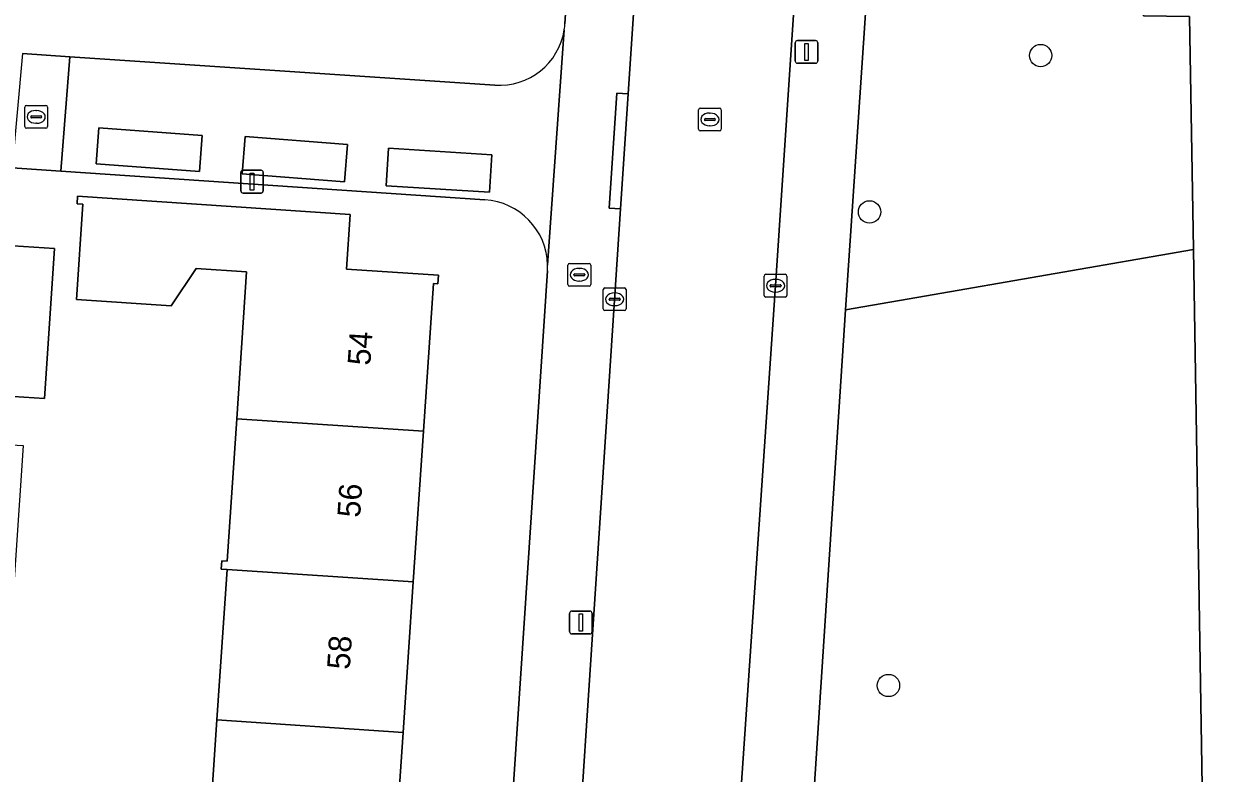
# Model space of a CAD drawing. Extents: x 161848 to 162726, y 385382 to 386521.
# Drawn here: x 162105.8 to 162158.3, y 385774.9 to 385807.8 of the extents above; entities that cross this region are included whole.
import ezdxf

# ---------------------------------------------------------------- set-up
doc = ezdxf.new("R2010")
doc.units = 0
for name, color, linetype in [('IMGEO_Boom', 7, 'Continuous'), ('IMGEO_Brandkraan', 7, 'Continuous'), ('IMGEO_Erf', 7, 'Continuous'), ('IMGEO_Groenvoorziening', 7, 'Continuous'), ('IMGEO_Kolk', 7, 'Continuous'), ('IMGEO_Lichtmast', 7, 'Continuous'), ('IMGEO_Pand', 7, 'Continuous'), ('IMGEO_Pand_nummerreeks', 7, 'Continuous'), ('IMGEO_Parkeervlak_open', 7, 'Continuous'), ('IMGEO_Rijbaan_lokaal_open', 7, 'Continuous'), ('IMGEO_Rioolput', 7, 'Continuous'), ('IMGEO_Voetpad_halfverhard', 7, 'Continuous'), ('IMGEO_Voetpad_open', 7, 'Continuous'), ('IMGEO_Woonerf_open', 7, 'Continuous')]:
    doc.layers.add(name, color=color, linetype=linetype)

msp = doc.modelspace()

# ---------------------------------------------------------------- linework, layer by layer
at = {"layer": 'IMGEO_Boom'}
for centre in [(162150.402, 385806.424), (162142.896, 385799.563), (162143.726, 385778.781)]:
    msp.add_circle(centre, 0.489, dxfattribs=at)
at = {"layer": 'IMGEO_Brandkraan'}
for p, q in [((162129.663, 385796.378), (162129.663, 385797.23)), ((162129.738, 385797.304), (162130.59, 385797.304)), ((162130.151, 385797.084), (162130.176, 385797.084)), ((162130.664, 385797.23), (162130.664, 385796.378)), ((162129.922, 385796.798), (162129.922, 385796.81)), ((162130.36, 385796.761), (162129.962, 385796.761)), ((162129.965, 385796.847), (162130.363, 385796.847)), ((162130.174, 385796.524), (162130.149, 385796.524)), ((162130.406, 385796.81), (162130.406, 385796.798)), ((162130.59, 385796.304), (162129.738, 385796.304))]:
    msp.add_line(p, q, dxfattribs=at)
for points in [[(162129.663, 385796.378), (162129.663, 385797.23)], [(162129.738, 385797.304), (162130.59, 385797.304)], [(162130.664, 385797.23), (162130.664, 385796.378)], [(162130.59, 385796.304), (162129.738, 385796.304)]]:
    msp.add_lwpolyline(points, dxfattribs=at)
for centre, radius, start, end in [((162129.74, 385797.228), 0.0765, 91.552, 178.448), ((162129.74, 385797.228), 0.0765, 91.552, 178.448), ((162130.588, 385797.228), 0.0765, 1.552, 88.448), ((162130.588, 385797.228), 0.0765, 1.552, 88.448), ((162129.962, 385796.807), 0.0403, 85.8775, 175.7526), ((162129.959, 385796.797), 0.0366, 178.938, 274.7102), ((162130.363, 385796.804), 0.043, 264.8664, 352.4533), ((162130.367, 385796.809), 0.0386, 1.7309, 96.639), ((162129.74, 385796.38), 0.0765, 181.552, 268.448), ((162129.74, 385796.38), 0.0765, 181.552, 268.448), ((162130.588, 385796.38), 0.0765, 271.552, 358.448), ((162130.588, 385796.38), 0.0765, 271.552, 358.448)]:
    msp.add_arc(centre, radius, start, end, dxfattribs=at)
for centre, major_axis, ratio, start_param, end_param in [((162130.15, 385796.804), (-0.387, 0.002), 0.722429, 4.712389, 7.853982), ((162130.175, 385796.804), (-0.39, 0.002), 0.717154, 1.570796, 4.712389)]:
    msp.add_ellipse(centre, major_axis=major_axis, ratio=ratio, start_param=start_param, end_param=end_param, dxfattribs=at)
at = {"layer": 'IMGEO_Erf'}
for points in [[(162129.533, 385807.812), (162132.809, 385856.832)], [(162105.74, 385806.512), (162107.807, 385806.373), (162126.458, 385805.124)], [(162126.021, 385800.096), (162107.418, 385801.352), (162105.286, 385801.495), (162104.182, 385801.57), (162103.952, 385798.168), (162107.135, 385797.957), (162106.7, 385791.372), (162103.517, 385791.583), (162103.367, 385789.451), (162105.762, 385789.318), (162105.439, 385784.505), (162105.109, 385779.574), (162102.716, 385779.735), (162102.474, 385776.123), (162104.871, 385776.017), (162104.554, 385771.291), (162104.23, 385766.445), (162101.833, 385766.551), (162100.851, 385751.751), (162123.16, 385750.258)], [(162113.836, 385770.929), (162114.264, 385777.274), (162114.709, 385783.871), (162114.456, 385783.888), (162114.48, 385784.253), (162114.711, 385784.237), (162115.133, 385790.489), (162115.568, 385796.933), (162113.349, 385797.082), (162112.251, 385795.446), (162108.101, 385795.726), (162108.383, 385799.9), (162108.129, 385799.917), (162108.152, 385800.25), (162120.107, 385799.443), (162119.946, 385797.053), (162123.981, 385796.781), (162123.956, 385796.404), (162123.761, 385796.417), (162123.324, 385789.937), (162122.878, 385783.33), (162122.432, 385776.723), (162121.986, 385770.116)], [(162125.095, 385750.985), (162125.671, 385751.883), (162125.822, 385752.589), (162128.766, 385796.974)]]:
    msp.add_lwpolyline(points, dxfattribs=at)
for centre, radius, start, end in [((162126.654, 385808.002), 2.885, 266.096, 351.118), ((162126.828, 385807.98), 2.71, 351.0214, 356.4462), ((162125.84, 385797.169), 2.932, 1.1876, 86.4666), ((162126.038, 385797.166), 2.734, 355.9736, 1.3412)]:
    msp.add_arc(centre, radius, start, end, dxfattribs=at)
at = {"layer": 'IMGEO_Groenvoorziening'}
msp.add_lwpolyline([(162157.103, 385797.911), (162156.935, 385808.144), (162154.917, 385808.163), (162153.602, 385814.866), (162152.92, 385815.252), (162143.498, 385813.15), (162143.016, 385812.624), (162141.848, 385795.27), (162144.975, 385795.811)], close=True, dxfattribs=at)
msp.add_lwpolyline([(162141.331, 385748.75), (162142.003, 385748.615), (162152.519, 385747.611), (162152.549, 385749.34), (162152.561, 385750), (162152.889, 385768.789), (162157.58, 385768.924), (162157.103, 385797.911), (162144.975, 385795.811), (162141.848, 385795.27), (162138.994, 385751.625), (162139.021, 385751.25), (162139.116, 385750.837), (162139.274, 385750.446), (162139.555, 385750)], dxfattribs=at)
at = {"layer": 'IMGEO_Kolk'}
for p, q in [((162105.835, 385803.309), (162105.835, 385804.161)), ((162105.91, 385804.235), (162106.762, 385804.235)), ((162106.323, 385804.015), (162106.348, 385804.015)), ((162106.836, 385804.161), (162106.836, 385803.309)), ((162106.094, 385803.729), (162106.094, 385803.741)), ((162106.532, 385803.692), (162106.134, 385803.692)), ((162106.137, 385803.778), (162106.535, 385803.778)), ((162106.346, 385803.455), (162106.321, 385803.455)), ((162106.578, 385803.741), (162106.578, 385803.729)), ((162106.762, 385803.235), (162105.91, 385803.235)), ((162138.272, 385795.898), (162138.272, 385796.75)), ((162138.347, 385796.824), (162139.199, 385796.824)), ((162138.76, 385796.604), (162138.785, 385796.604)), ((162139.273, 385796.75), (162139.273, 385795.898)), ((162131.212, 385795.305), (162131.212, 385796.157)), ((162131.287, 385796.231), (162132.139, 385796.231)), ((162131.7, 385796.011), (162131.725, 385796.011)), ((162132.213, 385796.157), (162132.213, 385795.305)), ((162138.531, 385796.318), (162138.531, 385796.33)), ((162138.969, 385796.281), (162138.571, 385796.281)), ((162138.574, 385796.367), (162138.972, 385796.367)), ((162138.783, 385796.044), (162138.758, 385796.044)), ((162139.015, 385796.33), (162139.015, 385796.318)), ((162131.471, 385795.725), (162131.471, 385795.737)), ((162131.909, 385795.688), (162131.511, 385795.688)), ((162131.514, 385795.774), (162131.912, 385795.774)), ((162131.723, 385795.451), (162131.698, 385795.451)), ((162131.955, 385795.737), (162131.955, 385795.725)), ((162139.199, 385795.824), (162138.347, 385795.824)), ((162132.139, 385795.231), (162131.287, 385795.231))]:
    msp.add_line(p, q, dxfattribs=at)
for points in [[(162105.835, 385803.309), (162105.835, 385804.161)], [(162105.91, 385804.235), (162106.762, 385804.235)], [(162106.836, 385804.161), (162106.836, 385803.309)], [(162106.762, 385803.235), (162105.91, 385803.235)], [(162138.272, 385795.898), (162138.272, 385796.75)], [(162138.347, 385796.824), (162139.199, 385796.824)], [(162139.273, 385796.75), (162139.273, 385795.898)], [(162131.212, 385795.305), (162131.212, 385796.157)], [(162131.287, 385796.231), (162132.139, 385796.231)], [(162132.213, 385796.157), (162132.213, 385795.305)], [(162139.199, 385795.824), (162138.347, 385795.824)], [(162132.139, 385795.231), (162131.287, 385795.231)]]:
    msp.add_lwpolyline(points, dxfattribs=at)
for centre, radius, start, end in [((162105.912, 385804.159), 0.0765, 91.552, 178.448), ((162105.912, 385804.159), 0.0765, 91.552, 178.448), ((162106.76, 385804.159), 0.0765, 1.552, 88.448), ((162106.76, 385804.159), 0.0765, 1.552, 88.448), ((162105.912, 385803.311), 0.0765, 181.552, 268.448), ((162105.912, 385803.311), 0.0765, 181.552, 268.448), ((162106.134, 385803.738), 0.0403, 85.8775, 175.7526), ((162106.131, 385803.728), 0.0366, 178.938, 274.7102), ((162106.535, 385803.735), 0.043, 264.8664, 352.4533), ((162106.539, 385803.74), 0.0386, 1.7309, 96.639), ((162106.76, 385803.311), 0.0765, 271.552, 358.448), ((162106.76, 385803.311), 0.0765, 271.552, 358.448), ((162138.349, 385796.748), 0.0765, 91.552, 178.448), ((162138.349, 385796.748), 0.0765, 91.552, 178.448), ((162139.197, 385796.748), 0.0765, 1.552, 88.448), ((162139.197, 385796.748), 0.0765, 1.552, 88.448), ((162131.289, 385796.155), 0.0765, 91.552, 178.448), ((162131.289, 385796.155), 0.0765, 91.552, 178.448), ((162132.137, 385796.155), 0.0765, 1.552, 88.448), ((162132.137, 385796.155), 0.0765, 1.552, 88.448), ((162138.571, 385796.327), 0.0403, 85.8775, 175.7526), ((162138.568, 385796.317), 0.0366, 178.938, 274.7102), ((162138.972, 385796.324), 0.043, 264.8664, 352.4533), ((162138.976, 385796.329), 0.0386, 1.7309, 96.639), ((162131.511, 385795.734), 0.0403, 85.8775, 175.7526), ((162131.508, 385795.724), 0.0366, 178.938, 274.7102), ((162131.912, 385795.731), 0.043, 264.8664, 352.4533), ((162131.916, 385795.736), 0.0386, 1.7309, 96.639), ((162138.349, 385795.9), 0.0765, 181.552, 268.448), ((162138.349, 385795.9), 0.0765, 181.552, 268.448), ((162139.197, 385795.9), 0.0765, 271.552, 358.448), ((162139.197, 385795.9), 0.0765, 271.552, 358.448), ((162131.289, 385795.307), 0.0765, 181.552, 268.448), ((162131.289, 385795.307), 0.0765, 181.552, 268.448), ((162132.137, 385795.307), 0.0765, 271.552, 358.448), ((162132.137, 385795.307), 0.0765, 271.552, 358.448)]:
    msp.add_arc(centre, radius, start, end, dxfattribs=at)
for centre, major_axis, ratio, start_param, end_param in [((162106.322, 385803.735), (-0.387, 0.002), 0.722429, 4.712389, 7.853982), ((162106.347, 385803.735), (-0.39, 0.002), 0.717154, 1.570796, 4.712389), ((162138.759, 385796.324), (-0.387, 0.002), 0.722429, 4.712389, 7.853982), ((162138.784, 385796.324), (-0.39, 0.002), 0.717154, 1.570796, 4.712389), ((162131.699, 385795.731), (-0.387, 0.002), 0.722429, 4.712389, 7.853982), ((162131.724, 385795.731), (-0.39, 0.002), 0.717154, 1.570796, 4.712389)]:
    msp.add_ellipse(centre, major_axis=major_axis, ratio=ratio, start_param=start_param, end_param=end_param, dxfattribs=at)
at = {"layer": 'IMGEO_Lichtmast'}
for p, q in [((162139.635, 385806.185), (162139.635, 385806.985)), ((162139.635, 385806.985), (162139.635, 385806.185)), ((162139.735, 385807.085), (162140.525, 385807.085)), ((162140.525, 385807.085), (162139.735, 385807.085)), ((162140.625, 385806.985), (162140.625, 385806.185)), ((162140.625, 385806.185), (162140.625, 385806.985)), ((162140.525, 385806.085), (162139.735, 385806.085)), ((162139.735, 385806.085), (162140.525, 385806.085)), ((162115.31, 385800.492), (162115.31, 385801.292)), ((162115.31, 385801.292), (162115.31, 385800.492)), ((162115.41, 385801.392), (162116.2, 385801.392)), ((162116.2, 385801.392), (162115.41, 385801.392)), ((162116.3, 385801.292), (162116.3, 385800.492)), ((162116.3, 385800.492), (162116.3, 385801.292)), ((162116.2, 385800.392), (162115.41, 385800.392)), ((162115.41, 385800.392), (162116.2, 385800.392)), ((162129.733, 385781.147), (162129.733, 385781.947)), ((162129.733, 385781.947), (162129.733, 385781.147)), ((162129.833, 385782.047), (162130.623, 385782.047)), ((162130.623, 385782.047), (162129.833, 385782.047)), ((162130.723, 385781.947), (162130.723, 385781.147)), ((162130.723, 385781.147), (162130.723, 385781.947)), ((162130.623, 385781.047), (162129.833, 385781.047)), ((162129.833, 385781.047), (162130.623, 385781.047))]:
    msp.add_line(p, q, dxfattribs=at)
for points in [[(162140.055, 385806.96), (162140.205, 385806.96), (162140.205, 385806.21), (162140.055, 385806.21), (162140.055, 385806.96)], [(162115.73, 385801.267), (162115.88, 385801.267), (162115.88, 385800.517), (162115.73, 385800.517), (162115.73, 385801.267)], [(162130.153, 385781.922), (162130.303, 385781.922), (162130.303, 385781.172), (162130.153, 385781.172), (162130.153, 385781.922)]]:
    msp.add_lwpolyline(points, dxfattribs=at)
for centre, start, end in [((162139.735, 385806.985), 90, 180), ((162139.735, 385806.985), 90, 180), ((162140.525, 385806.985), 0, 90), ((162140.525, 385806.985), 360, 90), ((162139.735, 385806.185), 180, 270), ((162139.735, 385806.185), 180, 270), ((162140.525, 385806.185), 270, 0), ((162140.525, 385806.185), 270, 0), ((162115.41, 385801.292), 90, 180), ((162115.41, 385801.292), 90, 180), ((162116.2, 385801.292), 0, 90), ((162116.2, 385801.292), 360, 90), ((162115.41, 385800.492), 180, 270), ((162115.41, 385800.492), 180, 270), ((162116.2, 385800.492), 270, 0), ((162116.2, 385800.492), 270, 0), ((162129.833, 385781.947), 90, 180), ((162129.833, 385781.947), 90, 180), ((162130.623, 385781.947), 0, 90), ((162130.623, 385781.947), 360, 90), ((162129.833, 385781.147), 180, 270), ((162129.833, 385781.147), 180, 270), ((162130.623, 385781.147), 270, 0), ((162130.623, 385781.147), 270, 0)]:
    msp.add_arc(centre, 0.1, start, end, dxfattribs=at)
at = {"layer": 'IMGEO_Pand'}
for points in [[(162123.324, 385789.937), (162123.761, 385796.417), (162123.956, 385796.404), (162123.981, 385796.781), (162119.946, 385797.053), (162120.107, 385799.443), (162108.152, 385800.25), (162108.129, 385799.917), (162108.383, 385799.9), (162108.101, 385795.726), (162112.251, 385795.446), (162113.349, 385797.082), (162115.568, 385796.933), (162115.133, 385790.489)], [(162107.135, 385797.957), (162103.952, 385798.168), (162103.517, 385791.583), (162106.7, 385791.372)], [(162122.878, 385783.33), (162123.324, 385789.937), (162115.133, 385790.489), (162114.711, 385784.237), (162114.48, 385784.253), (162114.456, 385783.888), (162114.709, 385783.871)], [(162122.432, 385776.723), (162122.878, 385783.33), (162114.709, 385783.871), (162114.264, 385777.274)], [(162114.264, 385777.274), (162113.836, 385770.929), (162113.597, 385770.946), (162113.579, 385770.683), (162121.986, 385770.116), (162122.432, 385776.723)]]:
    msp.add_lwpolyline(points, close=True, dxfattribs=at)
at = {"layer": 'IMGEO_Parkeervlak_open'}
for points in [[(162113.508, 385801.339), (162113.625, 385802.916), (162109.087, 385803.253), (162108.97, 385801.676)], [(162119.861, 385800.89), (162119.988, 385802.521), (162115.5, 385802.87), (162115.373, 385801.239)], [(162126.227, 385800.426), (162126.33, 385802.074), (162121.793, 385802.358), (162121.69, 385800.71)]]:
    msp.add_lwpolyline(points, close=True, dxfattribs=at)
at = {"layer": 'IMGEO_Rijbaan_lokaal_open'}
for points in [[(162138.772, 385796.328), (162140.044, 385815.501), (162142.706, 385855.491), (162145.383, 385895.531), (162146.681, 385914.982), (162149.256, 385954.021), (162150.691, 385975.187), (162143.703, 385975.556), (162132.307, 385804.741), (162131.97, 385799.695), (162128.863, 385752.339), (162128.687, 385751.25), (162128.645, 385751.095), (162128.505, 385750.663), (162128.216, 385750), (162128.164, 385749.886), (162128.109, 385749.773), (162128.043, 385749.646), (162127.974, 385749.52), (162127.442, 385748.75)], [(162135.705, 385751.411), (162138.772, 385796.328)]]:
    msp.add_lwpolyline(points, dxfattribs=at)
at = {"layer": 'IMGEO_Rioolput'}
for p, q in [((162135.392, 385803.193), (162135.392, 385804.045)), ((162135.467, 385804.119), (162136.319, 385804.119)), ((162135.88, 385803.899), (162135.905, 385803.899)), ((162136.393, 385804.045), (162136.393, 385803.193)), ((162135.651, 385803.613), (162135.651, 385803.625)), ((162136.089, 385803.576), (162135.691, 385803.576)), ((162135.694, 385803.662), (162136.092, 385803.662)), ((162135.903, 385803.339), (162135.878, 385803.339)), ((162136.135, 385803.625), (162136.135, 385803.613)), ((162136.319, 385803.119), (162135.467, 385803.119))]:
    msp.add_line(p, q, dxfattribs=at)
for points in [[(162135.392, 385803.193), (162135.392, 385804.045)], [(162135.467, 385804.119), (162136.319, 385804.119)], [(162136.393, 385804.045), (162136.393, 385803.193)], [(162136.319, 385803.119), (162135.467, 385803.119)]]:
    msp.add_lwpolyline(points, dxfattribs=at)
for centre, radius, start, end in [((162135.469, 385804.043), 0.0765, 91.552, 178.448), ((162135.469, 385804.043), 0.0765, 91.552, 178.448), ((162136.317, 385804.043), 0.0765, 1.552, 88.448), ((162136.317, 385804.043), 0.0765, 1.552, 88.448), ((162135.691, 385803.622), 0.0403, 85.8775, 175.7526), ((162135.688, 385803.612), 0.0366, 178.938, 274.7102), ((162136.092, 385803.619), 0.043, 264.8664, 352.4533), ((162136.096, 385803.624), 0.0386, 1.7309, 96.639), ((162135.469, 385803.195), 0.0765, 181.552, 268.448), ((162135.469, 385803.195), 0.0765, 181.552, 268.448), ((162136.317, 385803.195), 0.0765, 271.552, 358.448), ((162136.317, 385803.195), 0.0765, 271.552, 358.448)]:
    msp.add_arc(centre, radius, start, end, dxfattribs=at)
for centre, major_axis, ratio, start_param, end_param in [((162135.879, 385803.619), (-0.387, 0.002), 0.722429, 4.712389, 7.853982), ((162135.904, 385803.619), (-0.39, 0.002), 0.717154, 1.570796, 4.712389)]:
    msp.add_ellipse(centre, major_axis=major_axis, ratio=ratio, start_param=start_param, end_param=end_param, dxfattribs=at)
at = {"layer": 'IMGEO_Voetpad_halfverhard'}
msp.add_lwpolyline([(162155.575, 385873.467), (162156.134, 385857.272), (162156.736, 385819.213), (162156.209, 385818.61), (162143.943, 385815.882), (162143.259, 385816.251), (162143.016, 385812.624), (162143.498, 385813.15), (162152.92, 385815.252), (162153.602, 385814.866), (162154.917, 385808.163), (162156.935, 385808.144), (162157.103, 385797.911), (162157.58, 385768.924), (162157.893, 385750), (162157.941, 385747.093), (162160.44, 385746.854), (162160.391, 385750), (162160.103, 385768.548), (162159.557, 385805.784), (162158.695, 385864.488)], dxfattribs=at)
at = {"layer": 'IMGEO_Voetpad_open'}
for points in [[(162155.02, 385994.519), (162151.991, 385994.826), (162151.8, 385991.555), (162151.765, 385990.953), (162151.583, 385988.219), (162152.076, 385988.182), (162151.821, 385984.433), (162151.333, 385984.469), (162150.691, 385975.187), (162149.256, 385954.021), (162146.681, 385914.982), (162145.383, 385895.531), (162142.706, 385855.491), (162140.044, 385815.501), (162138.772, 385796.328), (162135.705, 385751.411)], [(162139.555, 385750), (162139.274, 385750.446), (162139.116, 385750.837), (162139.021, 385751.25), (162138.994, 385751.625), (162141.848, 385795.27), (162143.016, 385812.624), (162143.259, 385816.251), (162145.819, 385855.414), (162147.017, 385873.732), (162147.381, 385879.245), (162149.729, 385914.341), (162151.07, 385934.388), (162151.3, 385937.797), (162153.083, 385964.982), (162153.342, 385968.931), (162155.02, 385994.519)], [(162131.97, 385799.695), (162131.472, 385799.728), (162131.809, 385804.774), (162132.307, 385804.741), (162143.703, 385975.556)], [(162132.809, 385856.832), (162129.533, 385807.812)], [(162129.505, 385807.557), (162128.772, 385797.23)], [(162123.516, 385750.26), (162128.164, 385749.886), (162128.216, 385750), (162128.505, 385750.663), (162128.645, 385751.095), (162128.687, 385751.25), (162128.863, 385752.339), (162131.97, 385799.695)], [(162128.766, 385796.974), (162125.822, 385752.589), (162125.671, 385751.883), (162125.095, 385750.985)]]:
    msp.add_lwpolyline(points, dxfattribs=at)
msp.add_lwpolyline([(162131.97, 385799.695), (162132.307, 385804.741), (162131.809, 385804.774), (162131.472, 385799.728)], close=True, dxfattribs=at)
for centre, radius, start, end in [((162126.828, 385807.98), 2.71, 351.0214, 356.4462), ((162126.038, 385797.166), 2.734, 355.9736, 1.3412)]:
    msp.add_arc(centre, radius, start, end, dxfattribs=at)
at = {"layer": 'IMGEO_Woonerf_open'}
for points in [[(162128.772, 385797.23), (162129.505, 385807.557)], [(162126.458, 385805.124), (162107.807, 385806.373), (162107.418, 385801.352), (162126.021, 385800.096)]]:
    msp.add_lwpolyline(points, dxfattribs=at)
for points in [[(162107.807, 385806.373), (162105.74, 385806.512), (162105.286, 385801.495), (162107.418, 385801.352)], [(162113.508, 385801.339), (162108.97, 385801.676), (162109.087, 385803.253), (162113.625, 385802.916)], [(162119.988, 385802.521), (162119.861, 385800.89), (162115.373, 385801.239), (162115.5, 385802.87)], [(162121.793, 385802.358), (162126.33, 385802.074), (162126.227, 385800.426), (162121.69, 385800.71)]]:
    msp.add_lwpolyline(points, close=True, dxfattribs=at)
for centre, radius, start, end in [((162126.654, 385808.002), 2.885, 266.096, 351.118), ((162125.84, 385797.169), 2.932, 1.1876, 86.4666)]:
    msp.add_arc(centre, radius, start, end, dxfattribs=at)

# ---------------------------------------------------------------- texts
at = {"layer": 'IMGEO_Pand_nummerreeks'}
for s, p in [('54', (162120.992, 385792.803)), ('56', (162120.542, 385786.129)), ('58', (162120.091, 385779.459))]:
    msp.add_text(s, height=1, rotation=86.1402, dxfattribs=at).set_placement(p)

doc.saveas('drawing.dxf')
